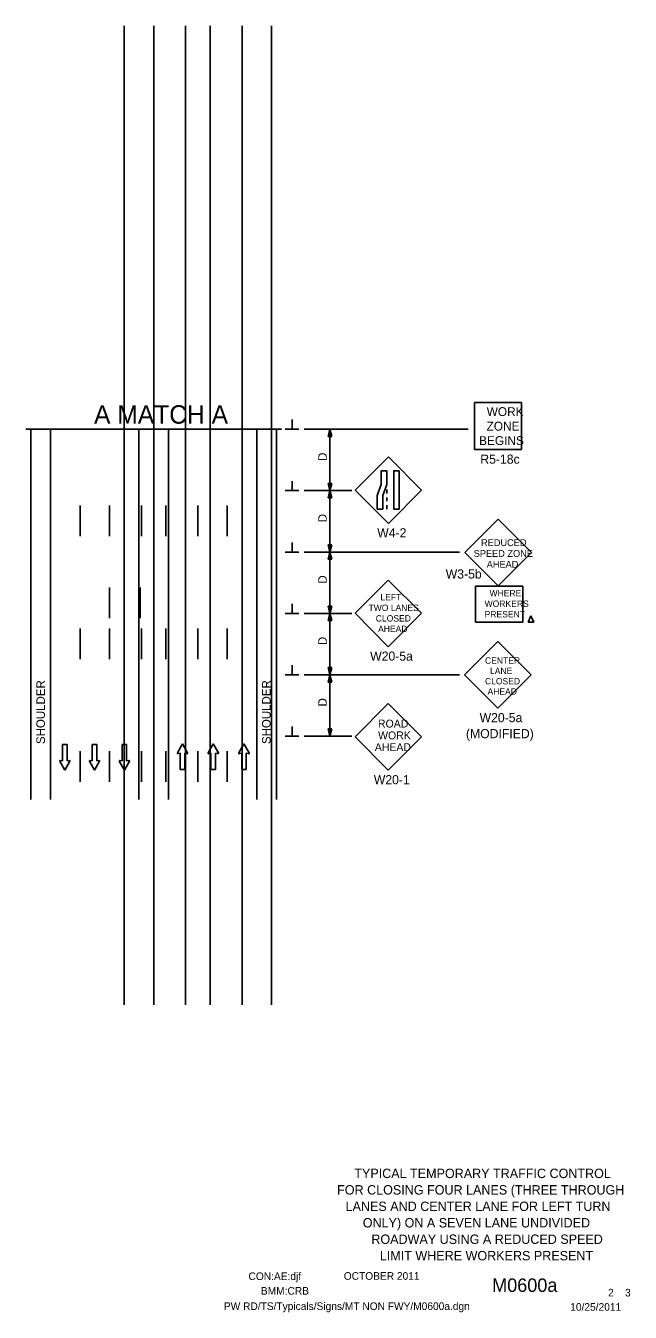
# Model space of a CAD drawing. Extents: x 16724 to 19504, y 5662 to 6979.
# Drawn here: x 17938 to 18431, y 5932 to 6979 of the extents above; entities that cross this region are included whole.
import ezdxf

# ---------------------------------------------------------------- set-up
doc = ezdxf.new("R2010")
doc.units = 0
for name, color, linetype in [('ALI_LEGAL_EX', 7, 'Continuous'), ('BORDER', 7, 'Continuous'), ('BORDER_SIGNAL_WO', 7, 'Continuous'), ('MT_SCRATCH_LEVEL_E', 7, 'Continuous'), ('PAVT_EDGE_EX', 7, 'Continuous'), ('TRAFFIC_SIGNS_PR', 7, 'Continuous'), ('TYPICAL_TEXT_DIMEN_PR', 7, 'Continuous')]:
    doc.layers.add(name, color=color, linetype=linetype)

msp = doc.modelspace()

# ---------------------------------------------------------------- linework, layer by layer
at = {"layer": 'ALI_LEGAL_EX'}
for p, q in [((18018.4, 6182.2), (18018.4, 6979.4)), ((18018.4, 6182.2), (18018.4, 6979.4)), ((18042.4, 6182.2), (18042.4, 6979.4)), ((18042.4, 6182.2), (18042.4, 6979.4)), ((18068.4, 6182.2), (18068.4, 6979.4)), ((18068.4, 6182.2), (18068.4, 6979.4)), ((18088.4, 6182.2), (18088.4, 6979.4)), ((18088.4, 6182.2), (18088.4, 6979.4)), ((18114.4, 6182.2), (18114.4, 6979.4)), ((18114.4, 6182.2), (18114.4, 6979.4)), ((18138.4, 6182.2), (18138.4, 6979.4)), ((18138.4, 6182.2), (18138.4, 6979.4))]:
    msp.add_line(p, q, dxfattribs=at)
for points in [[(17982.4, 6563.7), (17982.4, 6588.7)], [(18006.4, 6563.7), (18006.4, 6588.7)], [(18032.4, 6563.7), (18032.4, 6588.7)], [(18052.4, 6563.7), (18052.4, 6588.7)], [(18078.4, 6563.7), (18078.4, 6588.7)], [(18102.4, 6563.7), (18102.4, 6588.7)], [(17982.4, 6463.7), (17982.4, 6488.7)], [(18006.4, 6463.7), (18006.4, 6488.7)], [(18032.4, 6463.7), (18032.4, 6488.7)], [(18052.4, 6463.7), (18052.4, 6488.7)], [(18078.4, 6463.7), (18078.4, 6488.7)], [(18102.4, 6463.7), (18102.4, 6488.7)], [(17982.4, 6363.7), (17982.4, 6388.7)], [(18006.4, 6363.7), (18006.4, 6388.7)], [(18032.4, 6363.7), (18032.4, 6388.7)], [(18052.4, 6363.7), (18052.4, 6388.7)], [(18078.4, 6363.7), (18078.4, 6388.7)], [(18102.4, 6363.7), (18102.4, 6388.7)]]:
    msp.add_lwpolyline(points, dxfattribs=at)
at = {"layer": 'MT_SCRATCH_LEVEL_E'}
for p, q in [((17971.8, 6394.2), (17968.1, 6394.2)), ((17968.1, 6394.2), (17968.1, 6380.9)), ((17971.8, 6394.2), (17968.1, 6394.2)), ((17968.1, 6394.2), (17968.1, 6380.9)), ((17971.8, 6380.9), (17971.8, 6394.2)), ((17971.8, 6380.9), (17971.8, 6394.2)), ((17996.1, 6394.2), (17992.3, 6394.2)), ((17992.3, 6394.2), (17992.3, 6380.9)), ((17996.1, 6394.2), (17992.3, 6394.2)), ((17992.3, 6394.2), (17992.3, 6380.9)), ((17996.1, 6380.9), (17996.1, 6394.2)), ((17996.1, 6380.9), (17996.1, 6394.2)), ((18020.3, 6394.2), (18016.6, 6394.2)), ((18016.6, 6394.2), (18016.6, 6380.9)), ((18020.3, 6394.2), (18016.6, 6394.2)), ((18016.6, 6394.2), (18016.6, 6380.9)), ((18020.3, 6380.9), (18020.3, 6394.2)), ((18020.3, 6380.9), (18020.3, 6394.2)), ((18065.9, 6394.6), (18061.7, 6387.4)), ((18065.9, 6394.6), (18061.7, 6387.4)), ((18070, 6387.4), (18065.9, 6394.6)), ((18070, 6387.4), (18065.9, 6394.6)), ((18090.9, 6394.6), (18086.8, 6387.4)), ((18090.9, 6394.6), (18086.8, 6387.4)), ((18095.1, 6387.4), (18090.9, 6394.6)), ((18095.1, 6387.4), (18090.9, 6394.6)), ((18116, 6394.6), (18111.9, 6387.4)), ((18116, 6394.6), (18111.9, 6387.4)), ((18120.2, 6387.4), (18116, 6394.6)), ((18120.2, 6387.4), (18116, 6394.6)), ((17965.8, 6380.5), (17970, 6373.3)), ((17965.8, 6380.5), (17970, 6373.3)), ((17968.1, 6380.9), (17966.3, 6381.2)), ((17968.1, 6380.9), (17966.3, 6381.2)), ((17970, 6373.3), (17974.1, 6380.5)), ((17970, 6373.3), (17974.1, 6380.5)), ((17973.6, 6381.2), (17971.8, 6380.9)), ((17973.6, 6381.2), (17971.8, 6380.9)), ((17990.1, 6380.5), (17994.2, 6373.3)), ((17990.1, 6380.5), (17994.2, 6373.3)), ((17992.3, 6380.9), (17990.6, 6381.2)), ((17992.3, 6380.9), (17990.6, 6381.2)), ((17994.2, 6373.3), (17998.3, 6380.5)), ((17994.2, 6373.3), (17998.3, 6380.5)), ((17997.9, 6381.2), (17996.1, 6380.9)), ((17997.9, 6381.2), (17996.1, 6380.9)), ((18014.3, 6380.5), (18018.5, 6373.3)), ((18014.3, 6380.5), (18018.5, 6373.3)), ((18016.6, 6380.9), (18014.8, 6381.2)), ((18016.6, 6380.9), (18014.8, 6381.2)), ((18018.5, 6373.3), (18022.6, 6380.5)), ((18018.5, 6373.3), (18022.6, 6380.5)), ((18022.1, 6381.2), (18020.3, 6380.9)), ((18022.1, 6381.2), (18020.3, 6380.9)), ((18062.2, 6386.7), (18064, 6387)), ((18062.2, 6386.7), (18064, 6387)), ((18064, 6387), (18064, 6373.7)), ((18064, 6387), (18064, 6373.7)), ((18067.7, 6373.7), (18067.7, 6387)), ((18067.7, 6387), (18069.5, 6386.7)), ((18067.7, 6373.7), (18067.7, 6387)), ((18067.7, 6387), (18069.5, 6386.7)), ((18087.3, 6386.7), (18089.1, 6387)), ((18087.3, 6386.7), (18089.1, 6387)), ((18089.1, 6387), (18089.1, 6373.7)), ((18089.1, 6387), (18089.1, 6373.7)), ((18092.8, 6373.7), (18092.8, 6387)), ((18092.8, 6387), (18094.6, 6386.7)), ((18092.8, 6373.7), (18092.8, 6387)), ((18092.8, 6387), (18094.6, 6386.7)), ((18112.4, 6386.7), (18114.2, 6387)), ((18112.4, 6386.7), (18114.2, 6387)), ((18114.2, 6387), (18114.2, 6373.7)), ((18114.2, 6387), (18114.2, 6373.7)), ((18117.9, 6373.7), (18117.9, 6387)), ((18117.9, 6387), (18119.7, 6386.7)), ((18117.9, 6373.7), (18117.9, 6387)), ((18117.9, 6387), (18119.7, 6386.7)), ((18064, 6373.7), (18067.7, 6373.7)), ((18064, 6373.7), (18067.7, 6373.7)), ((18089.1, 6373.7), (18092.8, 6373.7)), ((18089.1, 6373.7), (18092.8, 6373.7)), ((18114.2, 6373.7), (18117.9, 6373.7)), ((18114.2, 6373.7), (18117.9, 6373.7))]:
    msp.add_line(p, q, dxfattribs=at)
for centre, start, end in [((17966.2, 6380.7), 80.0362, 209.7731), ((17966.2, 6380.7), 80.0362, 209.7731), ((17973.7, 6380.7), 330.4248, 99.9638), ((17973.7, 6380.7), 330.4248, 99.9638), ((17990.5, 6380.7), 80.0362, 209.7731), ((17990.5, 6380.7), 80.0362, 209.7731), ((17997.9, 6380.7), 330.4248, 99.9638), ((17997.9, 6380.7), 330.4248, 99.9638), ((18014.8, 6380.7), 80.0362, 209.7731), ((18014.8, 6380.7), 80.0362, 209.7731), ((18022.2, 6380.7), 330.4248, 99.9638), ((18022.2, 6380.7), 330.4248, 99.9638), ((18062.1, 6387.1), 150.4248, 279.9638), ((18062.1, 6387.1), 150.4248, 279.9638), ((18069.6, 6387.1), 260.0362, 29.7731), ((18069.6, 6387.1), 260.0362, 29.7731), ((18087.2, 6387.1), 150.4248, 279.9638), ((18087.2, 6387.1), 150.4248, 279.9638), ((18094.7, 6387.1), 260.0362, 29.7731), ((18094.7, 6387.1), 260.0362, 29.7731), ((18112.3, 6387.1), 150.4248, 279.9638), ((18112.3, 6387.1), 150.4248, 279.9638), ((18119.8, 6387.1), 260.0362, 29.7731), ((18119.8, 6387.1), 260.0362, 29.7731)]:
    msp.add_arc(centre, 0.463, start, end, dxfattribs=at)
at = {"layer": 'PAVT_EDGE_EX'}
for p, q in [((17942.4, 6650.9), (17942.4, 6349.5)), ((17958.4, 6650.9), (17958.4, 6349.5)), ((18030.4, 6650.9), (18030.4, 6349.5)), ((18054.4, 6650.9), (18054.4, 6349.5)), ((18126.4, 6650.9), (18126.4, 6349.5)), ((18142.4, 6650.9), (18142.4, 6349.5))]:
    msp.add_line(p, q, dxfattribs=at)
for points in [[(18006.4, 6496.9), (18006.4, 6521.9)], [(18031.4, 6496.9), (18031.4, 6521.9)]]:
    msp.add_lwpolyline(points, dxfattribs=at)
at = {"layer": 'TRAFFIC_SIGNS_PR'}
for p, q in [((18303.8, 6634.3), (18303.8, 6672.7)), ((18303.8, 6672.7), (18342.2, 6672.7)), ((18342.2, 6634.3), (18342.2, 6672.7)), ((18303.8, 6634.3), (18342.2, 6634.3)), ((18233.7, 6628.5), (18206.5, 6601.3)), ((18260.8, 6601.3), (18233.7, 6628.5)), ((18206.5, 6601.3), (18233.7, 6574.2)), ((18232.4, 6601.8), (18232.4, 6598.6)), ((18233.7, 6574.2), (18260.8, 6601.3)), ((18232.4, 6595.4), (18232.4, 6592.2)), ((18232.4, 6589), (18232.4, 6585.8)), ((18323.1, 6577.6), (18296, 6550.4)), ((18350.3, 6550.4), (18323.1, 6577.6)), ((18296, 6550.4), (18323.1, 6523.3)), ((18323.1, 6523.3), (18350.3, 6550.4)), ((18233.6, 6528.1), (18206.5, 6501)), ((18260.8, 6501), (18233.6, 6528.1)), ((18304.8, 6523.1), (18343.2, 6523.1)), ((18304.8, 6493.8), (18304.8, 6523.1)), ((18343.2, 6493.8), (18343.2, 6523.1)), ((18206.5, 6501), (18233.6, 6473.8)), ((18233.6, 6473.8), (18260.8, 6501)), ((18304.8, 6493.8), (18343.2, 6493.8)), ((18322.9, 6478), (18295.7, 6450.9)), ((18350, 6450.9), (18322.9, 6478)), ((18295.7, 6450.9), (18322.9, 6423.7)), ((18322.9, 6423.7), (18350, 6450.9)), ((18233.6, 6427.6), (18206.5, 6400.4)), ((18260.8, 6400.4), (18233.6, 6427.6)), ((18206.5, 6400.4), (18233.6, 6373.3)), ((18233.6, 6373.3), (18260.8, 6400.4))]:
    msp.add_line(p, q, dxfattribs=at)
for points in [[(18232.4, 6617.1), (18232.4, 6605.9), (18229.1, 6597), (18229.1, 6585.8), (18224.6, 6585.8), (18224.6, 6597), (18227.9, 6605.9), (18227.9, 6617.1)], [(18242.5, 6617.1), (18242.5, 6585.8), (18238.1, 6585.8), (18238.1, 6617.1)]]:
    msp.add_lwpolyline(points, close=True, dxfattribs=at)
for points in [[(18349.9, 6498.8), (18347.7, 6493.8)], [(18347.7, 6493.8), (18349.9, 6498.8)], [(18352.1, 6493.8), (18349.9, 6498.8)], [(18349.9, 6498.8), (18352.1, 6493.8)], [(18347.7, 6493.8), (18352.1, 6493.8)], [(18352.1, 6493.8), (18347.7, 6493.8)]]:
    msp.add_lwpolyline(points, dxfattribs=at)
at = {"layer": 'TYPICAL_TEXT_DIMEN_PR'}
for p, q in [((18155.2, 6650.9), (18155.2, 6658.7)), ((17938.1, 6650.9), (18146.7, 6650.9)), ((18030.4, 6650.9), (18054.4, 6650.9)), ((18160.8, 6650.9), (18149.5, 6650.9)), ((18165, 6650.9), (18298.7, 6650.9)), ((18184.5, 6645), (18186, 6650.9)), ((18186, 6645), (18184.5, 6645)), ((18186, 6650.9), (18186, 6600.9)), ((18186, 6650.9), (18187.6, 6645)), ((18187.6, 6645), (18186, 6645)), ((18160.8, 6600.9), (18149.5, 6600.9)), ((18155.2, 6600.9), (18155.2, 6608.7)), ((18165, 6600.9), (18204, 6600.9)), ((18186, 6600.9), (18184.5, 6606.8)), ((18184.5, 6606.8), (18186, 6606.8)), ((18184.5, 6595), (18186, 6600.9)), ((18186, 6606.8), (18187.6, 6606.8)), ((18187.6, 6606.8), (18186, 6600.9)), ((18186, 6600.9), (18186, 6550.9)), ((18186, 6600.9), (18187.6, 6595)), ((18186, 6595), (18184.5, 6595)), ((18187.6, 6595), (18186, 6595)), ((18155.2, 6550.9), (18155.2, 6558.7)), ((18160.8, 6550.9), (18149.5, 6550.9)), ((18165, 6550.9), (18291.6, 6550.9)), ((18186, 6550.9), (18184.5, 6556.8)), ((18184.5, 6556.8), (18186, 6556.8)), ((18184.5, 6545), (18186, 6550.9)), ((18186, 6556.8), (18187.6, 6556.8)), ((18187.6, 6556.8), (18186, 6550.9)), ((18186, 6550.9), (18186, 6500.9)), ((18186, 6550.9), (18187.6, 6545)), ((18186, 6545), (18184.5, 6545)), ((18187.6, 6545), (18186, 6545)), ((18155.2, 6500.9), (18155.2, 6508.7)), ((18186, 6500.9), (18184.5, 6506.8)), ((18184.5, 6506.8), (18186, 6506.8)), ((18186, 6506.8), (18187.6, 6506.8)), ((18187.6, 6506.8), (18186, 6500.9)), ((18160.8, 6500.9), (18149.5, 6500.9)), ((18165, 6500.9), (18204, 6500.9)), ((18184.5, 6495), (18186, 6500.9)), ((18186, 6500.9), (18186, 6450.9)), ((18186, 6500.9), (18187.6, 6495)), ((18186, 6495), (18184.5, 6495)), ((18187.6, 6495), (18186, 6495)), ((18155.2, 6450.9), (18155.2, 6458.7)), ((18186, 6450.9), (18184.5, 6456.8)), ((18184.5, 6456.8), (18186, 6456.8)), ((18186, 6456.8), (18187.6, 6456.8)), ((18187.6, 6456.8), (18186, 6450.9)), ((18160.8, 6450.9), (18149.5, 6450.9)), ((18165, 6450.9), (18291.6, 6450.9)), ((18184.5, 6445), (18186, 6450.9)), ((18186, 6445), (18184.5, 6445)), ((18186, 6450.9), (18186, 6400.9)), ((18186, 6450.9), (18187.6, 6445)), ((18187.6, 6445), (18186, 6445)), ((18160.8, 6400.9), (18149.5, 6400.9)), ((18155.2, 6400.9), (18155.2, 6408.7)), ((18165, 6400.9), (18204, 6400.9)), ((18186, 6400.9), (18184.5, 6406.8)), ((18184.5, 6406.8), (18186, 6406.8)), ((18186, 6406.8), (18187.6, 6406.8)), ((18187.6, 6406.8), (18186, 6400.9))]:
    msp.add_line(p, q, dxfattribs=at)

# ---------------------------------------------------------------- texts
at = {"layer": 'BORDER'}
for s, p in [('TYPICAL TEMPORARY TRAFFIC CONTROL', (18205.9, 6041.1)), ('FOR CLOSING FOUR LANES (THREE THROUGH', (18191.9, 6027.7)), ('LANES AND CENTER LANE FOR LEFT TURN', (18198.8, 6014.3)), ('ONLY) ON A SEVEN LANE UNDIVIDED', (18212.8, 6000.9)), ('ROADWAY USING A REDUCED SPEED', (18219.8, 5987.5)), ('LIMIT WHERE WORKERS PRESENT', (18226.7, 5974.1))]:
    msp.add_text(s, height=7.647, dxfattribs=at).set_placement(p)
at = {"layer": 'BORDER_SIGNAL_WO'}
for s, height, p in [('CON:AE:djf', 6.2, (18119.7, 5958.1)), ('    OCTOBER 2011    ', 6.2, (18188.1, 5958.3)), ('BMM:CRB   ', 6.2, (18129.8, 5946.2)), ('    M0600a   ', 11, (18301.9, 5948.4)), (' 2    3 ', 6.2, (18410.4, 5944.7)), ('PW RD/TS/Typicals/Signs/MT NON FWY/M0600a.dgn    ', 6.2, (18099.6, 5933.7)), ('10/25/2011    ', 6.2, (18381.9, 5933.1))]:
    msp.add_text(s, height=height, dxfattribs=at).set_placement(p)
at = {"layer": 'TRAFFIC_SIGNS_PR'}
for s, height, p in [('WORK', 7.22, (18313.8, 6661.6)), ('ZONE', 7.22, (18313.7, 6649.8)), ('BEGINS', 7.22, (18307.6, 6638)), ('R5-18c', 7.44, (18308.6, 6622.8)), ('W4-2', 7.44, (18224.6, 6562.8)), ('REDUCED', 5.6, (18309.2, 6555.7)), ('SPEED ZONE', 5.6, (18303.2, 6546.9)), ('W3-5b', 7.44, (18280.4, 6529.3)), ('AHEAD', 5.6, (18313.8, 6538.1)), ('LEFT', 5.2, (18227.2, 6511.5)), ('WHERE', 5.2, (18316.1, 6514.8)), ('TWO LANES', 5.2, (18217.5, 6502.9)), ('WORKERS', 5.2, (18312.1, 6506.2)), ('CLOSED', 5.2, (18223.4, 6494.3)), ('PRESENT', 5.2, (18312.1, 6497.6)), ('AHEAD', 5.2, (18225.3, 6485.7)), ('W20-5a', 7.44, (18218.8, 6462.4)), ('CENTER', 5.2, (18312.4, 6459.9)), ('LANE', 5.2, (18316.5, 6451.5)), ('CLOSED', 5.2, (18312.4, 6443.1)), ('AHEAD', 5.2, (18314.5, 6434.7)), ('ROAD', 6.4, (18225.2, 6408)), ('W20-5a', 7.44, (18308, 6412.3)), ('WORK', 6.4, (18225.3, 6398.4)), ('(MODIFIED)', 7.44, (18296.9, 6399.3)), ('AHEAD', 6.4, (18222.6, 6388.8)), ('W20-1', 7.44, (18221.8, 6361.8))]:
    msp.add_text(s, height=height, dxfattribs=at).set_placement(p)
at = {"layer": 'TYPICAL_TEXT_DIMEN_PR'}
msp.add_text('A MATCH A', height=15, dxfattribs=at).set_placement((17993.8, 6655.4))
for s, p in [('D', (18183.5, 6625.1)), ('D', (18183.5, 6575.1)), ('D', (18183.5, 6525.1)), ('D', (18183.5, 6475.1)), ('SHOULDER', (17953.8, 6394.5)), ('SHOULDER', (18137.7, 6394.5)), ('D', (18183.5, 6425.1))]:
    msp.add_text(s, height=7, rotation=90, dxfattribs=at).set_placement(p)

doc.saveas('drawing.dxf')
